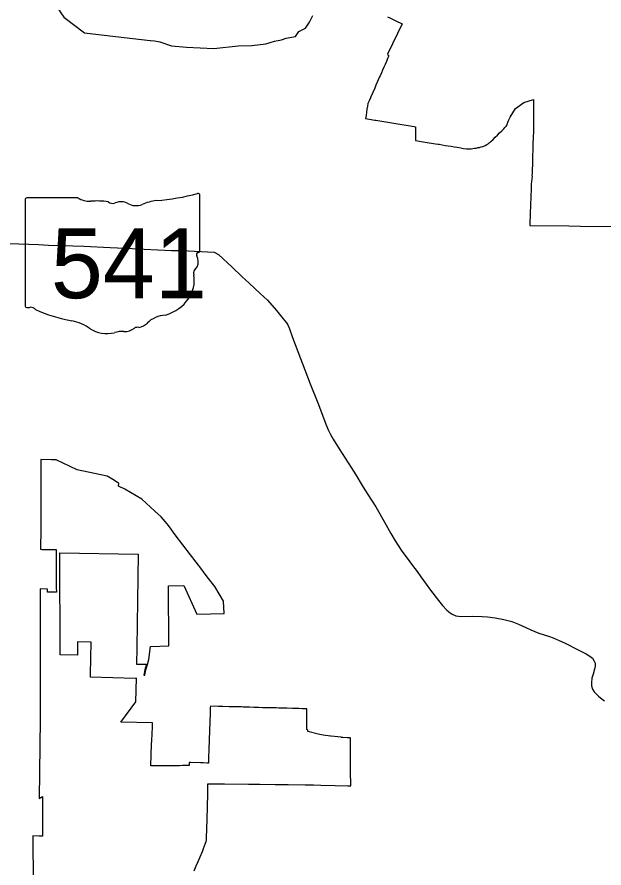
# Model space of a CAD drawing. Extents: x 2004415 to 2276415, y 751181 to 927181.
# Drawn here: x 2145735 to 2155148, y 818227 to 831882 of the extents above; entities that cross this region are included whole.
import ezdxf

# ---------------------------------------------------------------- set-up
doc = ezdxf.new("R2010")
doc.units = 0
for name, color, linetype in [('GM_X_Corporation', 7, 'Continuous'), ('GM_X_State_Route', 7, 'Continuous'), ('GM_X_State_Shield', 7, 'Continuous')]:
    doc.layers.add(name, color=color, linetype=linetype)

msp = doc.modelspace()

# ---------------------------------------------------------------- linework, layer by layer
at = {"layer": 'GM_X_Corporation'}
for points in [[(2146331, 832103), (2146485, 831881), (2146819, 831629), (2147313, 831571), (2147873, 831504), (2147874, 831504), (2147939, 831498), (2148024, 831483), (2148214, 831419), (2148451, 831399), (2148892, 831375), (2149280, 831421), (2149499, 831425), (2149725, 831450), (2149862, 831493), (2149975, 831514), (2150054, 831542), (2150199, 831568), (2150254, 831650), (2150364, 831704), (2150428, 831802), (2150478, 831908)], [(2151678, 831886), (2151714, 831868), (2151812, 831819), (2151910, 831771), (2151684, 831298), (2151675, 831279), (2151697, 831261), (2151678, 831214), (2151659, 831168), (2151638, 831122), (2151618, 831076), (2151598, 831028), (2151579, 830985), (2151559, 830941), (2151550, 830920), (2151492, 830788), (2151471, 830739), (2151410, 830604), (2151402, 830586), (2151382, 830539), (2151361, 830496), (2151354, 830452), (2151347, 830401), (2151340, 830353), (2151333, 830302), (2151325, 830253), (2151474, 830228), (2151489, 830225), (2151747, 830182), (2152105, 830124), (2152125, 830121), (2152124, 829901), (2152283, 829873), (2152445, 829848), (2152488, 829841), (2152504, 829840), (2152552, 829832), (2152602, 829823), (2152652, 829815), (2152695, 829809), (2152698, 829808), (2152747, 829799), (2152796, 829792), (2152850, 829781), (2152897, 829774), (2152943, 829769), (2152993, 829768), (2153018, 829769), (2153046, 829774), (2153074, 829776), (2153084, 829778), (2153099, 829780), (2153116, 829784), (2153126, 829786), (2153153, 829791), (2153163, 829794), (2153178, 829798), (2153205, 829805), (2153219, 829811), (2153245, 829821), (2153268, 829834), (2153292, 829849), (2153314, 829866), (2153318, 829868), (2153334, 829882), (2153370, 829919), (2153403, 829955), (2153439, 829987), (2153472, 830022), (2153508, 830058), (2153540, 830090), (2153557, 830109), (2153577, 830133), (2153594, 830152), (2153603, 830178), (2153613, 830205), (2153625, 830231), (2153643, 830276), (2153727, 830413), (2153862, 830508), (2154019, 830560), (2154017, 830446), (2154018, 830344), (2154019, 830262), (2154019, 830247), (2154018, 830221), (2154017, 830114), (2154016, 830028), (2154013, 829974), (2154008, 829822), (2154001, 829585), (2154001, 829582), (2153996, 829369), (2153993, 829340), (2153994, 829326), (2153982, 829202), (2153980, 829156), (2153979, 829123), (2153978, 829093), (2153976, 829030), (2153975, 829008), (2153969, 828855), (2153966, 828740), (2153959, 828536), (2153960, 828536), (2154587, 828530), (2154771, 828528), (2156336, 828513)], [(2148575, 818183), (2148607, 818260), (2148639, 818333), (2148673, 818408), (2148710, 818489), (2148717, 818508), (2148728, 818538), (2148759, 818623), (2148768, 818650), (2148774, 818678), (2148774, 818706), (2148785, 819010), (2148793, 819409), (2148794, 819437), (2148794, 819497), (2148793, 819578), (2149061, 819576), (2149448, 819571), (2149627, 819570), (2149873, 819567), (2150086, 819565), (2150357, 819562), (2150371, 819562), (2150488, 819559), (2150608, 819555), (2150839, 819551), (2151039, 819547), (2151086, 819546), (2151085, 819787), (2151085, 819887), (2151084, 820312), (2151080, 820313), (2151069, 820314), (2151041, 820316), (2151030, 820317), (2150962, 820321), (2150953, 820322), (2150939, 820323), (2150934, 820324), (2150773, 820343), (2150763, 820344), (2150643, 820359), (2150593, 820368), (2150564, 820374), (2150400, 820419), (2150400, 820438), (2150381, 820447), (2150381, 820462), (2150383, 820699), (2150383, 820733), (2150384, 820781), (2150313, 820783), (2150257, 820784), (2150187, 820786), (2150155, 820787), (2150061, 820790), (2150036, 820790), (2149998, 820791), (2149959, 820793), (2149935, 820793), (2149893, 820794), (2149872, 820795), (2149822, 820796), (2149809, 820796), (2149749, 820798), (2149746, 820798), (2149740, 820798), (2149683, 820799), (2149679, 820799), (2149609, 820801), (2149554, 820803), (2149533, 820804), (2149461, 820806), (2149411, 820807), (2149397, 820808), (2149381, 820808), (2149362, 820809), (2149334, 820810), (2149266, 820811), (2149140, 820815), (2149037, 820818), (2148967, 820819), (2148836, 820823), (2148835, 820804), (2148832, 820722), (2148831, 820704), (2148821, 820432), (2148817, 820279), (2148816, 820265), (2148810, 820144), (2148808, 819984), (2148808, 819909), (2148783, 819909), (2148720, 819912), (2148678, 819913), (2148520, 819919), (2148498, 819920), (2148497, 819870), (2148492, 819869), (2148440, 819869), (2148391, 819869), (2148340, 819868), (2148290, 819868), (2148240, 819868), (2148190, 819867), (2148137, 819867), (2148122, 819867), (2148107, 819867), (2148061, 819867), (2148011, 819866), (2147961, 819866), (2147911, 819866), (2147881, 819865), (2147894, 820214), (2147896, 820272), (2147910, 820484), (2147910, 820554), (2147398, 820567), (2147641, 820891), (2147649, 821270), (2147629, 821269), (2146915, 821287), (2146916, 821337), (2146924, 821849), (2146914, 821850), (2146703, 821854), (2146704, 821639), (2146428, 821646), (2146424, 823285), (2147677, 823264), (2147659, 821765), (2147653, 821496), (2147814, 821497), (2147787, 821408), (2147770, 821320), (2147786, 821321), (2147803, 821404), (2147829, 821494), (2147847, 821570), (2147878, 821781), (2148170, 821790), (2148165, 822755), (2148413, 822759), (2148617, 822302), (2149057, 822309), (2149045, 822506), (2148908, 822743), (2148808, 822873), (2148739, 822963), (2148697, 823017), (2148516, 823252), (2148274, 823575), (2148179, 823703), (2148141, 823750), (2148049, 823864), (2147943, 823954), (2147736, 824146), (2147466, 824303), (2147363, 824354), (2147367, 824402), (2147347, 824415), (2147272, 824460), (2147179, 824516), (2146699, 824618), (2146363, 824774), (2146303, 824775), (2146292, 824775), (2146287, 824775), (2146116, 824779), (2146116, 824072), (2146117, 823671), (2146111, 823341), (2146134, 823339), (2146180, 823339), (2146226, 823338), (2146272, 823337), (2146318, 823336), (2146364, 823336), (2146364, 823287), (2146365, 823167), (2146365, 823151), (2146365, 823101), (2146365, 823051), (2146365, 823001), (2146365, 822951), (2146365, 822901), (2146365, 822851), (2146365, 822801), (2146365, 822751), (2146365, 822726), (2146366, 822651), (2146239, 822653), (2146223, 822654), (2146223, 822703), (2146104, 822705), (2146104, 822656), (2146109, 820607), (2146092, 819339), (2146142, 819371), (2146142, 819193), (2146143, 818821), (2146143, 818737), (2146090, 818739), (2145989, 818743), (2145991, 818449), (2145992, 818271), (2145993, 818059)]]:
    msp.add_lwpolyline(points, dxfattribs=at)
at = {"layer": 'GM_X_State_Route'}
for p, q in [((2145609, 828246), (2146079, 828231)), ((2146079, 828231), (2146240, 828223)), ((2146240, 828223), (2146630, 828209)), ((2146630, 828209), (2146809, 828203)), ((2146809, 828203), (2147229, 828182)), ((2147229, 828182), (2147582, 828170)), ((2147582, 828170), (2147773, 828159)), ((2147773, 828159), (2148214, 828137)), ((2148214, 828137), (2148374, 828135)), ((2148374, 828135), (2148899, 828111))]:
    msp.add_line(p, q, dxfattribs=at)
msp.add_lwpolyline([(2148899, 828111), (2148965, 828071), (2149183, 827866), (2149339, 827720), (2149456, 827612), (2149636, 827444), (2149753, 827336), (2149899, 827170), (2150002, 827040), (2150056, 826976), (2150079, 826941), (2150104, 826881), (2150154, 826740), (2150439, 825998), (2150561, 825690), (2150587, 825622), (2150689, 825351), (2150730, 825249), (2150763, 825184), (2150807, 825106), (2150899, 824953), (2151094, 824651), (2151167, 824536), (2151271, 824364), (2151312, 824296), (2151421, 824129), (2151489, 824021), (2151624, 823784), (2151732, 823595), (2151801, 823478), (2151909, 823308), (2151992, 823197), (2152079, 823079), (2152153, 822984), (2152213, 822898), (2152297, 822782), (2152367, 822686), (2152492, 822520), (2152560, 822438), (2152627, 822364), (2152680, 822322), (2152716, 822299), (2152770, 822275), (2152816, 822266), (2152867, 822263), (2153039, 822267), (2153193, 822263), (2153280, 822258), (2153405, 822242), (2153542, 822215), (2153670, 822181), (2153780, 822139), (2153896, 822084), (2153974, 822050), (2154102, 821997), (2154272, 821942), (2154334, 821918), (2154429, 821879), (2154515, 821839), (2154743, 821724), (2154864, 821662), (2154920, 821628), (2154964, 821594), (2154986, 821555), (2155005, 821513), (2155006, 821467), (2154998, 821417), (2154973, 821339), (2154953, 821270), (2154947, 821200), (2154948, 821147), (2154966, 821096), (2154992, 821054), (2155016, 821024), (2155062, 820982), (2155118, 820936), (2155155, 820909)], dxfattribs=at)
at = {"layer": 'GM_X_State_Shield'}
for p, q in [((2145865, 828952), (2145865, 827250)), ((2146713, 828981), (2145893, 828981)), ((2148667, 828133), (2148667, 829023)), ((2148666, 828133), (2148667, 828133))]:
    msp.add_line(p, q, dxfattribs=at)
for centre, major_axis, start_param, end_param in [((2147669, 831300), (2971, 0), 4.814394, 5.042369), ((2148636, 829027), (31.2, 0), 6.141152, 7.989035), ((2145897, 828955), (32.5, 0), 1.712693, 3.28349), ((2146908, 829178), (315, 0), 4.042523, 4.731795), ((2147013, 828026), (1130, 0), 1.404758, 1.657858), ((2147269, 828964), (90.8, 0), 3.836095, 5.185415), ((2147403, 828767), (189, 0), 0.950623, 2.079405), ((2148048, 828461), (598, 0), 1.699011, 2.107814), ((2147647, 829037), (227, 0), 4.081561, 5.145723), ((2148660, 828068), (48.3, 0), 1.883978, 3.671073), ((2148633, 828130), (33.4, 0), 5.05454, 6.418171), ((2148352, 827955), (290, 0), 5.934695, 6.695948), ((2148778, 827761), (211, 0), 2.387724, 3.262537), ((2147835, 827648), (743, 0), 5.101752, 6.440018), ((2145897, 827247), (32.7, 0), 3.00124, 4.508301), ((2145902, 827421), (250, 0), 4.665946, 4.897461), ((2145953, 827152), (90.1, 0), 0.519207, 1.627899), ((2147091, 828681), (2146, 0), 4.195997, 4.488961), ((2146451, 826486), (671, 0), 0.823519, 1.323587), ((2148148, 826773), (407, 0), 1.647645, 2.488434), ((2147177, 827144), (426, 0), 4.026481, 4.996735), ((2147455, 827016), (227, 0), 4.691044, 5.507374), ((2147660, 826852), (63.9, 0), 1.147584, 2.315152), ((2147633, 827086), (240, 0), 4.937069, 5.64225), ((2147424, 826556), (350, 0), 1.495662, 1.94098)]:
    msp.add_ellipse(centre, major_axis=major_axis, ratio=0.8, start_param=start_param, end_param=end_param, dxfattribs=at)

# ---------------------------------------------------------------- texts
msp.add_text('541', height=1120.7, dxfattribs=at).set_placement((2146278, 827370))

doc.saveas('drawing.dxf')
